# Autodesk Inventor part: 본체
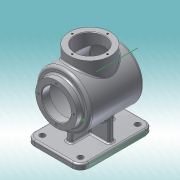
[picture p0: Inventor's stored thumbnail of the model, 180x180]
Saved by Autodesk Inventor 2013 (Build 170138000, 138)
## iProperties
Created: 2016-09
Part Number: 본체
Material: 알루미늄 6061
Document SubType Name: Modeling
Designer: dgall
Density: 2.71 g/cm^3
Mass: 972.332 g
Surface Area: 1283.36 cm^2
Volume: 358.794 cm^3
Author: dgall
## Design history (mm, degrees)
sketch "스케치1"
  geometry: L1 (0, 0)-(122, 0); L2 (0, 27)-(0, 38); L3 (0, 38)-(12, 38); L4 (12, 38)-(12, 50); L5 (12, 50)-(110.562, 50); L6 (108.661, 47)-(15, 47); L7 (15, 47)-(15, 27); L8 (0, 27)-(15, 27); A1 r 115 centre (7, 0) between (122, 0) and (110.562, 50); A2 r 112 centre (7, 0) between (119, 0) and (108.661, 47)
  constraints: 16 end point, 4 point on circle, 2 centre point, 2 parallel, 2 perpendicular, 2 point on line, 1 horizontal, 1 vertical alignment, 2 other
  dimensions: "d0" = 115 radius of A1; "d2" = 54 diameter of L8 L1; "d3" = 76 diameter of L3 L1; "d4" = 100 diameter of L5 L1; "d5" = 3 distance between parallel lines of L6 L5; "d6" = 12 distance of L2.end L3.end; "d7" = 110 distance from line of L1.end L4
revolve "회전1" sketch "스케치1" stored, may be unused: angle "d8" = 90 deg
fillet "모깎기1" dims "d9" = 5
node "작업 평면1"
fillet "모깎기2" dims "d10" = 2
node "작업축1"
node "작업 평면2"
sketch "스케치2"
  geometry: L1 (5.313, -50)-(-129.687, -50); L2 (-129.687, -50)-(-129.687, 50); L3 (-129.687, 50)-(5.313, 50); L4 (5.313, 50)-(5.313, -50); L5 (-17, 50)-(-107.374, 50) reference; 4 further points
  constraints: 8 end point, 3 midpoint, 2 parallel, 1 horizontal, 1 horizontal alignment, 1 perpendicular
  dimensions: "d12" = 135 distance of L2.end L3.end; "d14" = 100 distance of L1.end L2.end; "d15" = 67.5 distance from line of L2 point (-62.187, 50)
extrude "돌출1" join sketch "스케치2" distance "d16" = 10; taper "d17" = 0 deg
node "작업 평면3"
sketch "스케치3"
  geometry: L1 (22.313, 32)-(112.687, 32) reference; L2 (29.573, 33.7)-(27.5, 10); L3 (0, 0)-(0, 10) reference; L4 (135, 10)-(0, 10) reference; L5 (107.5, 10)-(27.5, 10); L6 (107.5, 10)-(105.427, 33.7); L7 (105.427, 33.7)-(29.573, 33.7); L8 (22.313, 132)-(112.687, 132) reference; 4 further points
  constraints: 8 end point, 4 midpoint, 1 coincident, 1 collinear, 1 parallel
  dimensions: "d21" = 80 distance of L2.end L5.start; "d85" = 95 deg angle of L4 L2; "d87" = 95 deg angle of L4 L6; "d89" = 23.7 distance between parallel lines of L4 L7
extrude "돌출2" join sketch "스케치3" stored distance "d24" = 10; taper "d25" = 0 deg
node "작업 평면4"
sketch "스케치4"
  geometry: L1 (10, 0)-(10, 100) reference; L2 (52, 90)-(10, 90); L3 (52, 10)-(10, 10); L4 (10, 10)-(10, 90); A1 r 50 centre (82, 50) between (52, 90) and (52, 10) reference; A2 r 53.268 centre (87.177, 50) between (52, 90) and (52, 10); 1 further point
  constraints: 6 end point, 4 point on circle, 2 perpendicular, 2 point on line, 1 centre point, 1 collinear, 1 parallel
  dimensions: "d26" = 80 distance between parallel lines of L3 L2; "d27" = 53.26766 radius of A2
extrude "돌출3" join sketch "스케치4" stored distance "d28" = 10; taper "d29" = 0 deg
node "작업 평면5"
sketch "스케치5"
  geometry: L1 (-5.313, 50)-(-5.313, -50) reference; L2 (12, -45)-(12, 45) reference; C1 r 38 at (62, 0); 1 further point
  constraints: 1 centre point, 1 horizontal alignment
  dimensions: "d32" = 76 diameter of C1; "d83" = 50 distance from line of L2 C1.centre
extrude "돌출4" join sketch "스케치5" stored distance "d33" = 10; taper "d34" = 0 deg
sketch "스케치6"
  geometry: C1 r 38 at (0, 0) reference; 2 further points
  constraints: 1 coincident
hole "구멍1" sketch "스케치6" at (0, 0) diameter "d35" = 54; stored, may be unused: countersink angle "d39" = 90 deg, drill point angle "d41" = 118 deg; dims "d36" = 6, "d37" = 4, "d38" = 2, "d40" = 50
chamfer "모따기1" distance "d42" = 1; stored, may be unused: second distance "d43" = 2, angle "d44" = 45 deg
sketch "스케치7"
  geometry: C1 r 38 at (0, 0) reference; 2 further points
  constraints: 1 vertical alignment
  dimensions: "d45" = 32.5 distance of C1.centre point (0, 32.5)
hole "구멍2" sketch "스케치7" at (0, 32.5) diameter "d46" = 3.242; stored, may be unused: countersink angle "d50" = 90 deg, drill point angle "d52" = 118 deg; dims "d47" = 8, "d48" = 4, "d49" = 2, "d51" = 10
sketch "스케치8"
  geometry: C1 r 38 at (0, 0) reference; 1 further point
  constraints: 1 vertical alignment
  dimensions: "d56" = 32.5 distance of C1.centre point (0, 32.5)
hole "구멍3" sketch "스케치8" at (0, 32.5) diameter "d57" = 3.242; stored, may be unused: countersink angle "d61" = 90 deg, drill point angle "d63" = 118 deg; dims "d58" = 8, "d59" = 4, "d60" = 2, "d62" = 10
fillet "모깎기3" dims "d67" = 15
fillet "모깎기4" dims "d68" = 3
fillet "모깎기5" dims "d69" = 3
fillet "모깎기6" dims "d70" = 3
fillet "모깎기7" dims "d71" = 3
fillet "모깎기8" dims "d72" = 3
sketch "스케치9"
  geometry: A1 r 12 centre (114.687, -35) between (114.687, -47) and (126.687, -35) reference; A2 r 12 centre (114.687, 35) between (126.687, 35) and (114.687, 47) reference; A3 r 12 centre (9.687, 35) between (9.687, 47) and (-2.313, 35) reference; A4 r 12 centre (9.687, -35) between (-2.313, -35) and (9.687, -47) reference; 5 further points
  constraints: 4 coincident
hole "구멍4" sketch "스케치9" at (9.687, 35), (114.687, 35), (114.687, -35), (9.687, -35) diameter "d73" = 10; stored, may be unused: countersink angle "d77" = 90 deg, drill point angle "d79" = 118 deg; dims "d74" = 8, "d75" = 4, "d76" = 2, "d78" = 10
node "작업 평면6"
sketch "스케치10"
  geometry: 2 further points
  constraints: 1 coincident, 1 other
feature "엠보싱1" sketch "스케치10" dims "d0" = 115, "d2" = 54, "d3" = 76, "d4" = 100, "d5" = 3, "d6" = 12, "d7" = 110, "d80" = 0.5, "d81" = 0
fillet "모깎기9" dims "d82" = 3
sketch "스케치11"
  geometry: L1 (0, 7)-(105, 7) reference; L2 (0, 0)-(0, 7) reference; L3 (0, 0)-(105, 0) reference; L4 (105, 7)-(105, 0) reference; L5 (14.313, 147)-(90.313, 147) reference; 1 further point
node "솔리드1"
pattern_circular "원형 패턴1" dims angle "d54" = 360 deg
pattern_circular "원형 패턴2" dims angle "d65" = 360 deg
other parameters: "d11" = -82, "d30" = -147
